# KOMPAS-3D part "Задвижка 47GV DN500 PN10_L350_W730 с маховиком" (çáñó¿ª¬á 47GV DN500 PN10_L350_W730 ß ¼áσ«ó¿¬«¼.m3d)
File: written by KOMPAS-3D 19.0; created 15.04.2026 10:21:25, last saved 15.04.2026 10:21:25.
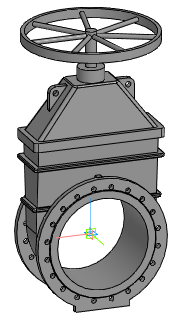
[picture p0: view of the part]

Document properties: Автор: Евгений; Полное имя файла: Z:\3.Личные\kachalov\3d для проектировщиков\2.1 Тип 47GV, 47GV.Z\Задвижка 47GV_DN40-DN600\stp_Задвижка 47GV\Задвижка 47GV DN500 PN10_L350_W730 с маховиком.m3d

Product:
- Part/product: Задвижка 47GV DN500 PN10_L350_W730 с маховиком

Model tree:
1. Операция без истории:1  (labels: Задвижка 47GV DN500 PN10_L350_W730 с маховиком)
